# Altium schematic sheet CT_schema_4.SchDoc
size 298 x 230 mm
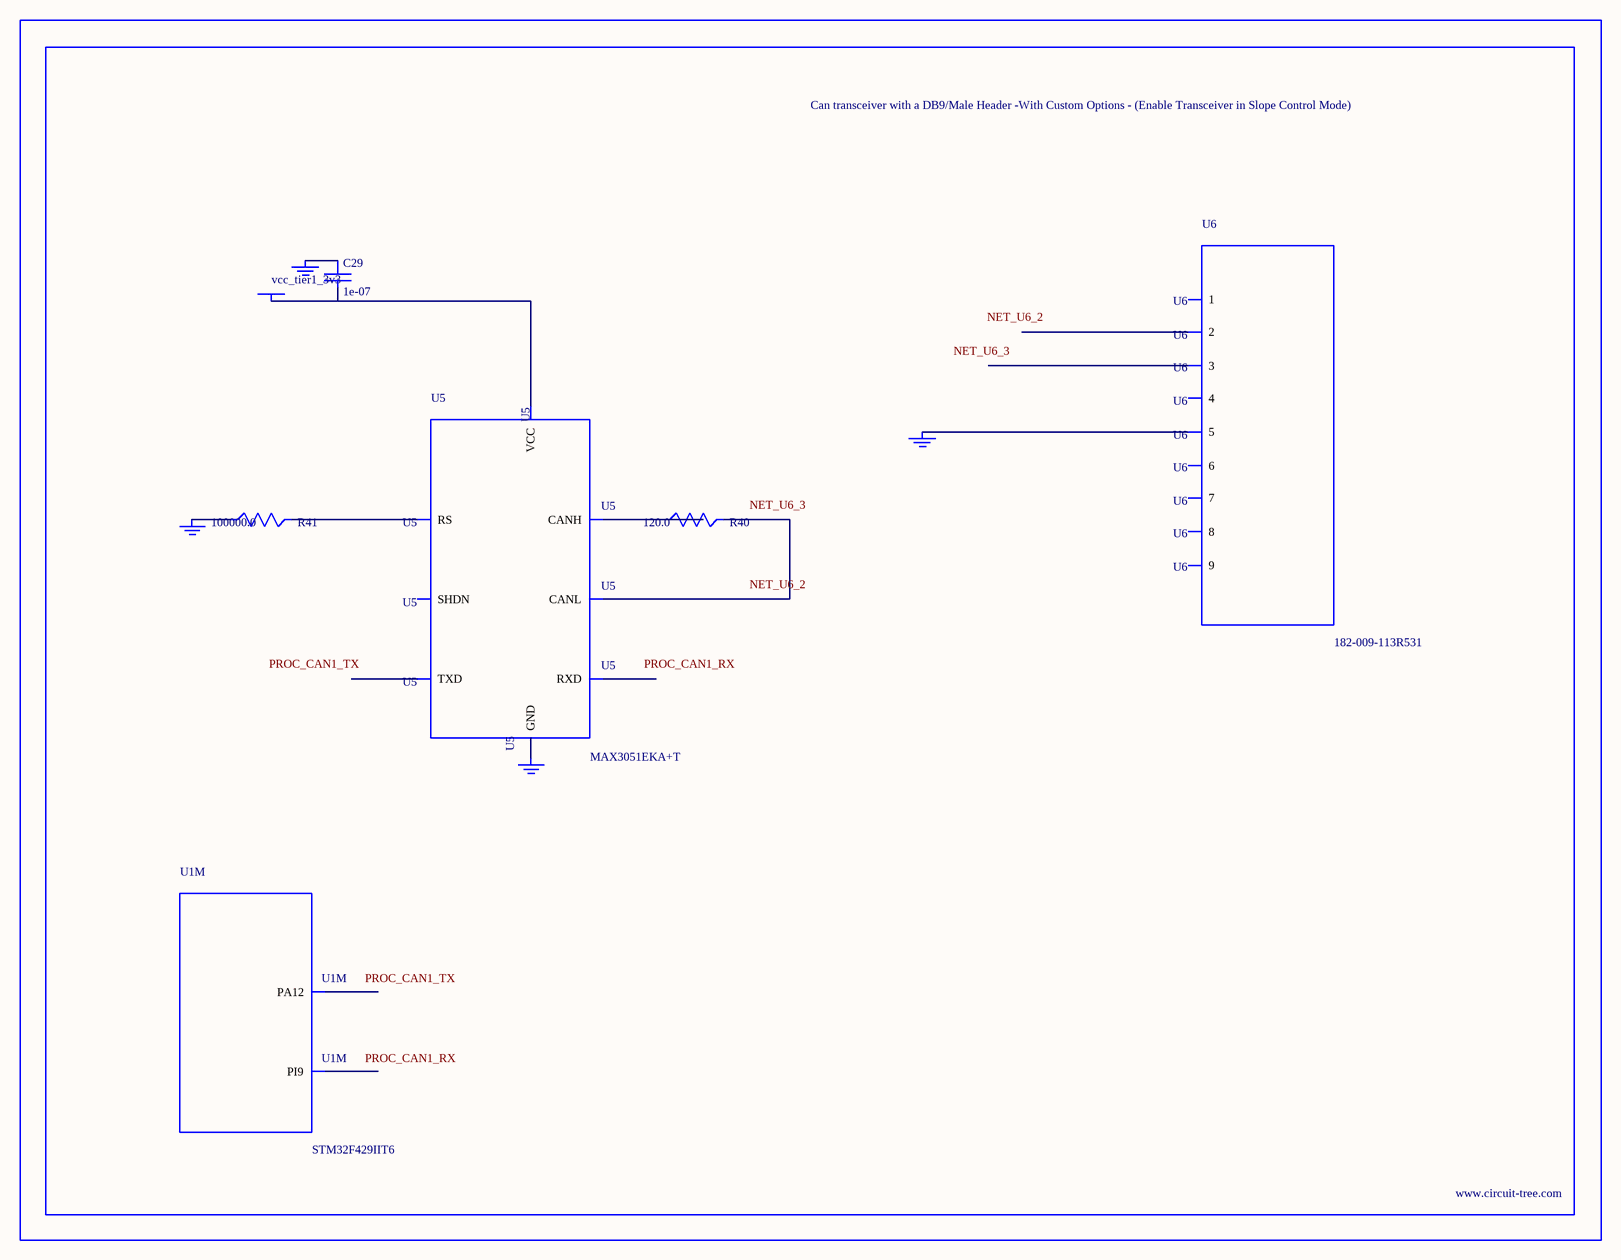
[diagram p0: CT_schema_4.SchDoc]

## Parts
BORDER3  (no value)
C29  1e-07  [C0402]
GND_INSTANCE_3_0  (no value)
GND_INSTANCE_3_1  (no value)
GND_INSTANCE_3_2  (no value)
GND_INSTANCE_3_3  (no value)
POWER_INSTANCE_3_0  vcc_tier1_3v3
R40  120.0  [R0603]
R41  100000.0  [R0603]
U1  STM32F429IIT6  [LQFP176]  (part M of 15)
U5  MAX3051EKA+T  [SOT-23-8]
U6  182-009-113R531  [182-009-MALE]

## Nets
NetC29_1: C29.1 GND_INSTANCE_3_0.0(GND)
NetC29_2: C29.2 POWER_INSTANCE_3_0.0(PWR) U5.3(VCC)
NetGND_INSTANCE_3_1_0: GND_INSTANCE_3_1.0(GND) R41.1
NetGND_INSTANCE_3_2_0: GND_INSTANCE_3_2.0(GND) U5.2(GND)
NetGND_INSTANCE_3_3_0: GND_INSTANCE_3_3.0(GND) U6.5
NetR40_1: R40.1 U5.7(CANH)
NetR40_2: R40.2 U5.6(CANL)
NetR41_2: R41.2 U5.8(RS)

Not connected (* = marked no-connect by the designer): U1 11(PI9) 123(PA12); U5 1(TXD) 4(RXD) 5(SHDN); U6 1 2 3 4 6 7 8 9

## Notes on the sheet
- Labels drawn without touching a wire or pin: NET_U6_2, NET_U6_3, PROC_CAN1_RX, PROC_CAN1_TX

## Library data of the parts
BORDER3 = BORDER_PAGE3
C29 = C0402C104K3RACTU
GND_INSTANCE_3_0-GND_INSTANCE_3_3 = GND
POWER_INSTANCE_3_0 = PWR
R40 = RC0603JR-07120RL
R41 = RC0603JR-07100KL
